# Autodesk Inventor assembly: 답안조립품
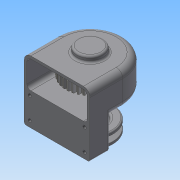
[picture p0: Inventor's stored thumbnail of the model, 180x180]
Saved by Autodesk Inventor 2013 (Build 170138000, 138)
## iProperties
Created: 2015-02
Part Number: 답안조립품
Document SubType Name: Assembly
Designer: Administrator
Author: Administrator
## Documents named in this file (14)
- C:\Documents and Settings\Administrator\바탕 화면\450214V1011\답안조립품.iam
- C:\Documents and Settings\Administrator\바탕 화면\450214V1011\1-본체.ipt
- C:\Documents and Settings\Administrator\바탕 화면\450214V1011\베어링 6001.ipt
- C:\Documents and Settings\Administrator\바탕 화면\450214V1011\축.ipt
- C:\Documents and Settings\Administrator\바탕 화면\450214V1011\키5x5.ipt
- C:\Documents and Settings\Administrator\바탕 화면\450214V1011\스퍼기어.ipt
- C:\Documents and Settings\Administrator\바탕 화면\450214V1011\축커버.ipt
- C:\Documents and Settings\Administrator\바탕 화면\450214V1011\M3x0.5.ipt
- C:\Documents and Settings\Administrator\바탕 화면\450214V1011\오일실.ipt
- C:\Documents and Settings\Administrator\바탕 화면\450214V1011\키4x4.ipt
- C:\Documents and Settings\Administrator\바탕 화면\450214V1011\4-V-벨트풀리.ipt
- C:\Documents and Settings\Administrator\바탕 화면\450214V1011\와샤.ipt
- C:\Documents and Settings\Administrator\바탕 화면\450214V1011\M5x0.8.ipt
- M5x0.8.ipt
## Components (7 placed, 4 different names)
1. 1-본체:1
2. 4-V-벨트풀리:1 — 각도:4
3. M5x0.8:1
4. M3x0.5:1
5. M3x0.5:2
6. M3x0.5:3
7. M3x0.5:4
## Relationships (1: Angle 1)
- 각도:4 [Angle]: 4-V-벨트풀리:1
